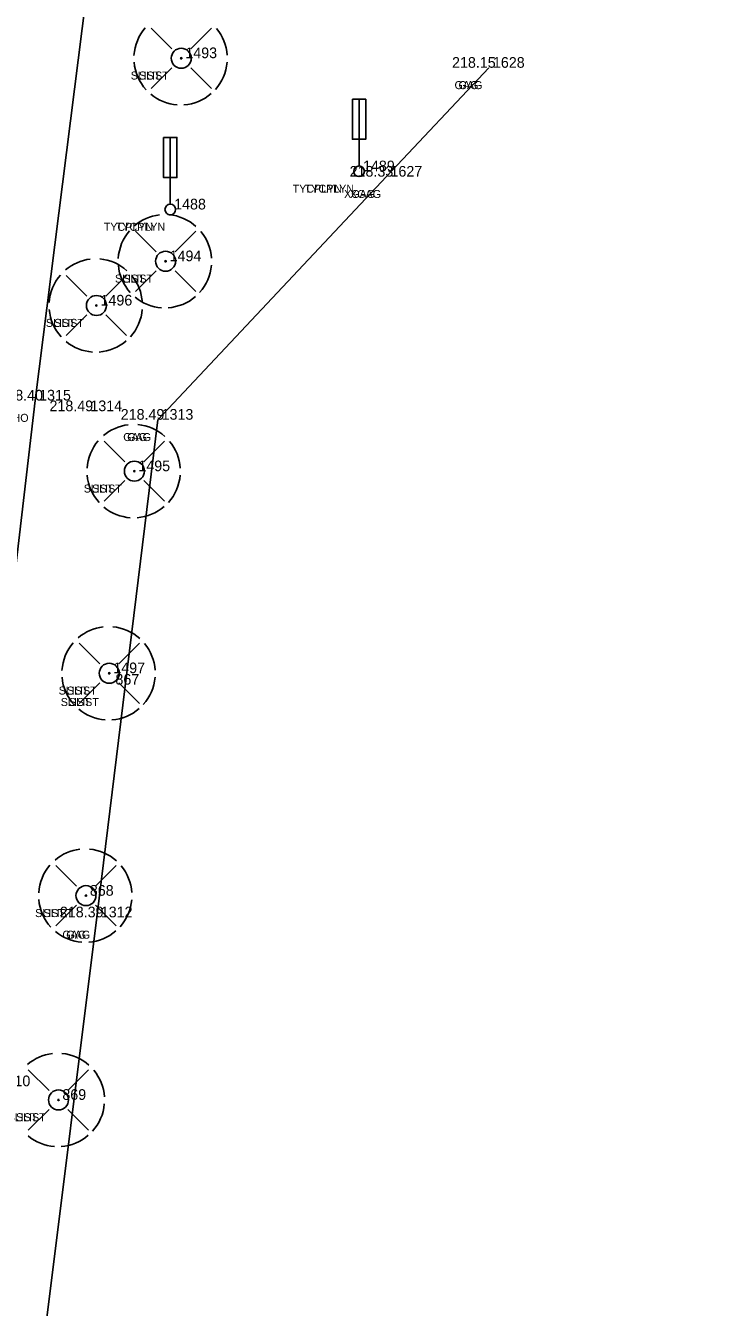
# Model space of a CAD drawing. Extents: x -471047 to -470889, y -1102859 to -1102000.
# Drawn here: x -470945.39 to -470919.5, y -1102458.3 to -1102410.26 of the extents above; entities that cross this region are included whole.
import ezdxf

# ---------------------------------------------------------------- set-up
doc = ezdxf.new("R2010")
doc.units = 0
for name, color, linetype in [('Vrstva 1', 7, 'Continuous'), ('Vrstva 11', 7, 'Continuous'), ('Vrstva 16', 7, 'Continuous'), ('Vrstva 34', 7, 'Continuous'), ('Vrstva 35', 7, 'Continuous'), ('Vrstva 36', 7, 'Continuous'), ('Vrstva 38', 7, 'Continuous'), ('Vrstva 6', 7, 'Continuous'), ('Vrstva 8', 7, 'Continuous')]:
    doc.layers.add(name, color=color, linetype=linetype)

msp = doc.modelspace()

# ---------------------------------------------------------------- linework, layer by layer
at = {"layer": 'Vrstva 1'}
for points in [[(-471040.344, -1102858.385), (-471031.676, -1102846.187), (-471026.357, -1102838.629), (-471023.212, -1102833.975), (-471019.21, -1102827.465), (-471016.861, -1102823.272), (-471013.099, -1102815.912), (-471010.824, -1102810.955), (-471007.329, -1102802.292), (-471005.34, -1102796.515), (-471002.842, -1102787.838), (-471001.3, -1102780.997), (-471000.19, -1102774.713), (-470999.247, -1102768.204), (-470998.794, -1102764.784), (-470997.199, -1102751.812), (-470994.899, -1102732.807), (-470992.551, -1102713.262), (-470990.326, -1102694.887), (-470988.122, -1102676.57), (-470985.812, -1102657.305), (-470983.537, -1102638.407), (-470981.386, -1102620.622), (-470979.843, -1102608.014), (-470976.377, -1102579.253), (-470972.945, -1102550.69), (-470970.475, -1102530.206), (-470967.905, -1102508.801), (-470965.053, -1102485.131), (-470962.734, -1102465.9), (-470960.173, -1102444.812), (-470957.795, -1102425.103), (-470954.965, -1102401.839), (-470953.834, -1102392.574), (-470952.33, -1102379.985), (-470950.744, -1102366.853), (-470948.978, -1102352.106), (-470947.037, -1102335.844), (-470944.949, -1102318.462), (-470944.013, -1102310.745), (-470942.39, -1102297.267), (-470939.519, -1102273.45), (-470937.593, -1102257.43), (-470936.064, -1102244.81), (-470934.114, -1102228.634), (-470931.621, -1102207.856), (-470929.536, -1102190.857), (-470926.572, -1102166.31), (-470924.91, -1102152.663), (-470923.413, -1102140.333), (-470921.923, -1102127.669), (-470921.155, -1102120.084), (-470920.446, -1102109.574), (-470919.912, -1102099.137), (-470919.63, -1102088.981), (-470919.523, -1102081.193), (-470919.563, -1102070.395), (-470919.714, -1102064.236), (-470920.134, -1102054.704), (-470920.462, -1102047.615), (-470920.599, -1102044.52), (-470920.743, -1102041.873), (-470921.125, -1102034.455), (-470921.774, -1102030.337), (-470922.418, -1102027.787), (-470923.734, -1102023.93), (-470924.872, -1102021.434), (-470926.752, -1102018.182), (-470927.953, -1102016.45), (-470929.616, -1102014.424), (-470932.252, -1102011.756), (-470935.111, -1102009.425), (-470938.391, -1102007.371), (-470942.651, -1102005.401)], [(-471041.328, -1102857.18), (-471032.144, -1102844.242), (-471027.583, -1102837.763), (-471024.388, -1102833.028), (-471020.451, -1102826.6), (-471018.089, -1102822.378), (-471014.542, -1102815.445), (-471012.233, -1102810.418), (-471009.247, -1102803.108), (-471006.795, -1102796.098), (-471004.315, -1102787.532), (-471002.782, -1102780.723), (-471001.674, -1102774.458), (-471000.75, -1102768.095), (-471000.28, -1102764.601), (-470998.692, -1102751.741), (-470996.378, -1102732.635), (-470994.028, -1102713.058), (-470991.808, -1102694.749), (-470989.616, -1102676.447), (-470987.284, -1102657.013), (-470985.031, -1102638.272), (-470982.87, -1102620.431), (-470981.334, -1102607.933), (-470977.881, -1102579.263), (-470974.429, -1102550.492), (-470971.964, -1102530.054), (-470969.391, -1102508.607), (-470966.54, -1102484.984), (-470964.231, -1102465.853), (-470961.679, -1102444.752), (-470959.304, -1102425.078), (-470956.455, -1102401.634), (-470955.339, -1102392.489), (-470953.812, -1102379.71), (-470952.249, -1102366.808), (-470950.479, -1102352.023), (-470948.536, -1102335.868), (-470946.426, -1102318.233), (-470945.493, -1102310.531), (-470943.864, -1102297.013), (-470940.984, -1102273.071), (-470939.078, -1102257.195), (-470937.559, -1102244.684), (-470935.592, -1102228.353), (-470933.101, -1102207.653), (-470931.011, -1102190.57), (-470928.046, -1102166.021), (-470926.409, -1102152.578), (-470924.898, -1102140.121), (-470923.427, -1102127.544), (-470922.647, -1102119.826), (-470921.919, -1102109.229), (-470921.42, -1102099.134), (-470921.127, -1102089.016), (-470921.023, -1102081.453), (-470921.061, -1102070.468), (-470921.209, -1102064.314), (-470921.666, -1102053.966), (-470922.156, -1102043.345), (-470922.299, -1102039.934), (-470922.637, -1102034.36), (-470923.091, -1102031.241), (-470923.847, -1102028.247), (-470925.083, -1102024.594), (-470926.222, -1102022.086), (-470928.04, -1102018.943), (-470929.138, -1102017.357), (-470930.929, -1102015.175), (-470933.062, -1102013.049), (-470936.379, -1102010.368), (-470939.169, -1102008.662), (-470942.899, -1102006.906), (-470945.661, -1102005.908)], [(-471043.557, -1102855.955), (-471035.129, -1102844.026), (-471029.872, -1102836.499), (-471026.577, -1102831.578), (-471022.675, -1102825.415), (-471020.123, -1102821.053), (-471016.667, -1102814.59), (-471014.208, -1102809.45), (-471011.177, -1102802.451), (-471008.55, -1102795.333), (-471006.082, -1102787.209), (-471004.464, -1102780.376), (-471003.265, -1102774.167), (-471002.327, -1102767.948), (-471001.636, -1102762.527), (-471000.297, -1102751.605), (-470997.959, -1102732.524), (-470995.602, -1102712.802), (-470993.412, -1102694.623), (-470991.21, -1102676.17), (-470988.891, -1102656.857), (-470986.625, -1102638.083), (-470984.455, -1102620.195), (-470982.936, -1102607.733), (-470979.497, -1102579.223), (-470976.023, -1102550.279), (-470973.554, -1102529.822), (-470970.991, -1102508.497), (-470968.146, -1102484.787), (-470965.835, -1102465.72), (-470963.284, -1102444.529), (-470960.91, -1102424.942), (-470958.043, -1102401.343), (-470956.946, -1102392.356), (-470955.396, -1102379.408), (-470953.851, -1102366.636), (-470952.049, -1102351.733), (-470950.124, -1102335.611), (-470948.034, -1102318.083), (-470947.094, -1102310.328), (-470945.421, -1102296.51), (-470942.58, -1102272.848), (-470940.675, -1102256.948), (-470939.176, -1102244.526), (-470937.187, -1102228.174), (-470934.708, -1102207.467), (-470932.621, -1102190.433), (-470929.634, -1102165.778), (-470928.004, -1102152.415), (-470926.45, -1102139.595), (-470925.003, -1102127.418), (-470924.249, -1102119.695), (-470923.515, -1102109.093), (-470923.018, -1102099.069), (-470922.711, -1102088.911), (-470922.643, -1102081.356), (-470922.797, -1102070.414), (-470923.018, -1102064.454), (-470923.52, -1102053.203), (-470923.823, -1102047.529), (-470924.123, -1102041.506), (-470924.462, -1102037.486), (-470924.934, -1102031.904), (-470925.664, -1102028.672), (-470926.771, -1102025.506), (-470927.959, -1102022.914), (-470929.674, -1102020.028), (-470930.76, -1102018.498), (-470932.447, -1102016.478), (-470935.215, -1102013.816), (-470937.644, -1102011.98), (-470940.381, -1102010.371), (-470943.968, -1102008.669), (-470947.145, -1102007.524), (-470950.874, -1102006.74)], [(-471044.756, -1102855.056), (-471036.376, -1102843.177), (-471031.167, -1102835.741), (-471027.859, -1102830.8), (-471023.934, -1102824.593), (-471021.43, -1102820.312), (-471018.011, -1102813.91), (-471015.536, -1102808.75), (-471012.578, -1102801.897), (-471009.95, -1102794.77), (-471007.561, -1102786.914), (-471005.936, -1102780.074), (-471004.727, -1102773.818), (-471003.828, -1102767.827), (-471003.121, -1102762.345), (-471001.787, -1102751.467), (-470999.446, -1102732.348), (-470997.073, -1102712.539), (-470994.902, -1102694.521), (-470992.696, -1102676.023), (-470990.376, -1102656.68), (-470988.131, -1102638.071), (-470985.947, -1102620.018), (-470984.417, -1102607.512), (-470980.993, -1102579.08), (-470977.514, -1102550.137), (-470975.048, -1102529.649), (-470972.488, -1102508.37), (-470969.618, -1102484.508), (-470967.34, -1102465.669), (-470964.767, -1102444.39), (-470962.402, -1102424.781), (-470959.534, -1102401.193), (-470958.432, -1102392.151), (-470956.883, -1102379.208), (-470955.335, -1102366.424), (-470953.535, -1102351.506), (-470951.606, -1102335.399), (-470949.519, -1102317.94), (-470948.575, -1102310.159), (-470946.889, -1102296.144), (-470944.056, -1102272.618), (-470942.139, -1102256.659), (-470940.657, -1102244.341), (-470938.638, -1102227.749), (-470936.19, -1102207.298), (-470934.102, -1102190.255), (-470931.124, -1102165.639), (-470929.492, -1102152.254), (-470927.915, -1102139.252), (-470926.46, -1102127.103), (-470925.74, -1102119.604), (-470925.012, -1102108.913), (-470924.523, -1102099.054), (-470924.217, -1102088.866), (-470924.148, -1102081.334), (-470924.301, -1102070.391), (-470924.518, -1102064.43), (-470924.97, -1102054.435), (-470925.588, -1102041.569), (-470925.963, -1102035.313), (-470926.405, -1102032.225), (-470927.078, -1102029.198), (-470928.123, -1102026.148), (-470929.318, -1102023.558), (-470930.84, -1102020.97), (-470931.868, -1102019.515), (-470933.443, -1102017.605), (-470936.26, -1102014.885), (-470938.429, -1102013.255), (-470941.213, -1102011.639), (-470944.847, -1102009.927), (-470947.723, -1102008.912), (-470951.444, -1102008.161), (-470954.511, -1102007.931), (-470957.895, -1102008.041)]]:
    msp.add_spline(points, degree=3, dxfattribs=at)
at = {"layer": 'Vrstva 11'}
for p, q in [((-470932.889, -1102413.02), (-470932.889, -1102415.52)), ((-470939.966, -1102414.452), (-470939.966, -1102416.952))]:
    msp.add_line(p, q, dxfattribs=at)
for points in [[(-470933.139, -1102413.02), (-470932.639, -1102413.02), (-470932.639, -1102414.52), (-470933.139, -1102414.52)], [(-470940.216, -1102414.452), (-470939.716, -1102414.452), (-470939.716, -1102415.952), (-470940.216, -1102415.952)]]:
    msp.add_lwpolyline(points, close=True, dxfattribs=at)
for centre in [(-470932.889, -1102415.719), (-470939.966, -1102417.151)]:
    msp.add_circle(centre, 0.2, dxfattribs=at)
at = {"layer": 'Vrstva 16'}
for p, q in [((-470939.91, -1102411.129), (-470940.686, -1102410.354)), ((-470939.2, -1102411.129), (-470938.426, -1102410.354)), ((-470939.91, -1102411.839), (-470940.686, -1102412.614)), ((-470939.2, -1102411.839), (-470938.426, -1102412.614)), ((-470940.498, -1102418.735), (-470941.274, -1102417.96)), ((-470939.788, -1102418.735), (-470939.014, -1102417.96)), ((-470940.498, -1102419.445), (-470941.274, -1102420.22)), ((-470939.788, -1102419.445), (-470939.014, -1102420.22)), ((-470943.09, -1102420.394), (-470943.864, -1102419.619)), ((-470942.38, -1102420.394), (-470941.604, -1102419.619)), ((-470943.09, -1102421.104), (-470943.864, -1102421.879)), ((-470942.38, -1102421.104), (-470941.604, -1102421.879)), ((-470941.668, -1102426.603), (-470942.442, -1102425.828)), ((-470940.958, -1102426.603), (-470940.182, -1102425.828)), ((-470941.668, -1102427.313), (-470942.442, -1102428.088)), ((-470940.958, -1102427.313), (-470940.182, -1102428.088)), ((-470942.61, -1102434.178), (-470943.384, -1102433.403)), ((-470941.9, -1102434.178), (-470941.124, -1102433.403)), ((-470942.61, -1102434.888), (-470943.384, -1102435.663)), ((-470941.9, -1102434.888), (-470941.124, -1102435.663)), ((-470943.482, -1102442.511), (-470944.256, -1102441.736)), ((-470942.772, -1102442.511), (-470941.996, -1102441.736)), ((-470943.482, -1102443.221), (-470944.256, -1102443.996)), ((-470942.772, -1102443.221), (-470941.996, -1102443.996)), ((-470944.512, -1102450.168), (-470945.288, -1102449.393)), ((-470943.802, -1102450.168), (-470943.028, -1102449.393)), ((-470944.512, -1102450.878), (-470945.288, -1102451.653)), ((-470943.802, -1102450.878), (-470943.028, -1102451.653))]:
    msp.add_line(p, q, dxfattribs=at)
for centre, radius in [((-470939.555, -1102411.484), 0.375), ((-470939.555, -1102411.484), 0.025), ((-470939.555, -1102411.484), 0.025), ((-470940.143, -1102419.09), 0.375), ((-470940.143, -1102419.09), 0.025), ((-470940.143, -1102419.09), 0.025), ((-470942.734, -1102420.749), 0.375), ((-470942.734, -1102420.749), 0.025), ((-470942.734, -1102420.749), 0.025), ((-470941.312, -1102426.958), 0.375), ((-470941.312, -1102426.958), 0.025), ((-470941.312, -1102426.958), 0.025), ((-470942.254, -1102434.533), 0.375), ((-470942.254, -1102434.533), 0.025), ((-470942.254, -1102434.533), 0.025), ((-470943.126, -1102442.866), 0.375), ((-470943.126, -1102442.866), 0.025), ((-470943.126, -1102442.866), 0.025), ((-470944.157, -1102450.523), 0.375), ((-470944.157, -1102450.523), 0.025), ((-470944.157, -1102450.523), 0.025)]:
    msp.add_circle(centre, radius, dxfattribs=at)
for centre, start, end in [((-470939.58, -1102411.484), 139.23, 176.4602), ((-470939.58, -1102411.484), 3.8615, 39.6013), ((-470939.58, -1102411.484), 184.9408, 222.2827), ((-470939.58, -1102411.484), 318.1086, 355.0481), ((-470939.58, -1102411.484), 274.1732, 310.7861), ((-470939.58, -1102411.484), 230.4703, 265.8356), ((-470940.169, -1102419.09), 96.7144, 130.447), ((-470940.169, -1102419.09), 48.1897, 84.9117), ((-470940.169, -1102419.09), 139.23, 176.4602), ((-470940.169, -1102419.09), 3.8615, 39.6013), ((-470942.759, -1102420.749), 96.7144, 130.447), ((-470942.759, -1102420.749), 48.1897, 84.9117), ((-470940.169, -1102419.09), 184.9408, 222.2827), ((-470940.169, -1102419.09), 318.1086, 355.0481), ((-470942.759, -1102420.749), 139.23, 176.4602), ((-470942.759, -1102420.749), 3.8615, 39.6013), ((-470940.169, -1102419.09), 230.4703, 265.8356), ((-470940.169, -1102419.09), 274.1732, 310.7861), ((-470942.759, -1102420.749), 184.9408, 222.2827), ((-470942.759, -1102420.749), 318.1086, 355.0481), ((-470942.759, -1102420.749), 230.4703, 265.8356), ((-470942.759, -1102420.749), 274.1732, 310.7861), ((-470941.338, -1102426.958), 96.7144, 130.447), ((-470941.338, -1102426.958), 48.1897, 84.9117), ((-470941.338, -1102426.958), 139.23, 176.4602), ((-470941.338, -1102426.958), 3.8615, 39.6013), ((-470941.338, -1102426.958), 184.9408, 222.2827), ((-470941.338, -1102426.958), 318.1086, 355.0481), ((-470941.338, -1102426.958), 230.4703, 265.8356), ((-470941.338, -1102426.958), 274.1732, 310.7861), ((-470942.28, -1102434.533), 96.7144, 130.447), ((-470942.28, -1102434.533), 48.1897, 84.9117), ((-470942.28, -1102434.533), 139.23, 176.4602), ((-470942.28, -1102434.533), 3.8615, 39.6013), ((-470942.28, -1102434.533), 184.9408, 222.2827), ((-470942.28, -1102434.533), 318.1086, 355.0481), ((-470942.28, -1102434.533), 274.1732, 310.7861), ((-470942.28, -1102434.533), 230.4703, 265.8356), ((-470943.152, -1102442.866), 96.7144, 130.447), ((-470943.152, -1102442.866), 48.1897, 84.9117), ((-470943.152, -1102442.866), 139.23, 176.4602), ((-470943.152, -1102442.866), 3.8615, 39.6013), ((-470943.152, -1102442.866), 184.9408, 222.2827), ((-470943.152, -1102442.866), 318.1086, 355.0481), ((-470943.152, -1102442.866), 230.4703, 265.8356), ((-470943.152, -1102442.866), 274.1732, 310.7861), ((-470944.182, -1102450.523), 96.7144, 130.447), ((-470944.182, -1102450.523), 48.1897, 84.9117), ((-470944.182, -1102450.523), 3.8615, 39.6013), ((-470944.182, -1102450.523), 318.1086, 355.0481), ((-470944.182, -1102450.523), 230.4703, 265.8356), ((-470944.182, -1102450.523), 274.1732, 310.7861)]:
    msp.add_arc(centre, 1.75, start, end, dxfattribs=at)
at = {"layer": 'Vrstva 34'}
for p, q in [((-470939.55, -1102411.48), (-470939.55, -1102411.48)), ((-470928.02, -1102411.84), (-470928.02, -1102411.84)), ((-470932.89, -1102415.72), (-470932.89, -1102415.72)), ((-470931.86, -1102415.92), (-470931.86, -1102415.92)), ((-470939.97, -1102417.15), (-470939.97, -1102417.15)), ((-470940.14, -1102419.09), (-470940.14, -1102419.09)), ((-470942.73, -1102420.75), (-470942.73, -1102420.75)), ((-470945.03, -1102424.31), (-470945.03, -1102424.31)), ((-470943.11, -1102424.71), (-470943.11, -1102424.71)), ((-470940.44, -1102425.03), (-470940.44, -1102425.03)), ((-470941.31, -1102426.96), (-470941.31, -1102426.96)), ((-470942.25, -1102434.53), (-470942.25, -1102434.53)), ((-470942.17, -1102434.96), (-470942.17, -1102434.96)), ((-470943.13, -1102442.87), (-470943.13, -1102442.87)), ((-470942.72, -1102443.68), (-470942.72, -1102443.68)), ((-470944.16, -1102450.52), (-470944.16, -1102450.52))]:
    msp.add_line(p, q, dxfattribs=at)
at = {"layer": 'Vrstva 6'}
for p, q in [((-470928.019, -1102411.838), (-470931.865, -1102415.917)), ((-470931.865, -1102415.917), (-470940.437, -1102425.028)), ((-470940.437, -1102425.028), (-470942.718, -1102443.675)), ((-470942.718, -1102443.675), (-470946.028, -1102470.224))]:
    msp.add_line(p, q, dxfattribs=at)
at = {"layer": 'Vrstva 8'}
for p, q in [((-470945.026, -1102424.313), (-470942.48, -1102404.12)), ((-470948.019, -1102449.764), (-470945.026, -1102424.313))]:
    msp.add_line(p, q, dxfattribs=at)

# ---------------------------------------------------------------- texts
at = {"layer": 'Vrstva 35'}
for s, p in [('SLIST', (-470941.45, -1102412.28)), ('SLIST', (-470941.139, -1102412.28)), ('GAG', (-470929.31, -1102412.64)), ('GAG', (-470929.159, -1102412.64)), ('TYCPLYN', (-470935.379, -1102416.52)), ('TYCPLYN', (-470934.929, -1102416.52)), ('XGAG', (-470933.45, -1102416.72)), ('XGAG', (-470933.224, -1102416.72)), ('TYCPLYN', (-470942.459, -1102417.95)), ('TYCPLYN', (-470942.009, -1102417.95)), ('SLIST', (-470942.04, -1102419.89)), ('SLIST', (-470941.729, -1102419.89)), ('SLIST', (-470944.63, -1102421.55)), ('SLIST', (-470944.319, -1102421.55)), ('CHO', (-470946.169, -1102425.11)), ('GAG', (-470941.73, -1102425.83)), ('GAG', (-470941.579, -1102425.83)), ('SLIST', (-470943.21, -1102427.76)), ('SLIST', (-470942.899, -1102427.76)), ('SLIST', (-470944.15, -1102435.33)), ('SLIST', (-470943.839, -1102435.33)), ('SLIST', (-470944.07, -1102435.76)), ('SLIST', (-470943.759, -1102435.76)), ('SLIST', (-470945.03, -1102443.67)), ('SLIST', (-470944.719, -1102443.67)), ('GAG', (-470944.01, -1102444.48)), ('GAG', (-470943.859, -1102444.48)), ('SLIST', (-470946.06, -1102451.32)), ('SLIST', (-470945.749, -1102451.32))]:
    msp.add_text(s, height=0.3, dxfattribs=at).set_placement(p)
at = {"layer": 'Vrstva 36'}
for s, p in [(' 1493', (-470939.55, -1102411.48)), (' 1628', (-470928.02, -1102411.84)), (' 1489', (-470932.89, -1102415.72)), (' 1627', (-470931.86, -1102415.92)), (' 1488', (-470939.97, -1102417.15)), (' 1494', (-470940.14, -1102419.09)), (' 1496', (-470942.73, -1102420.75)), (' 1315', (-470945.03, -1102424.31)), (' 1314', (-470943.11, -1102424.71)), (' 1313', (-470940.44, -1102425.03)), (' 1495', (-470941.31, -1102426.96)), (' 1497', (-470942.25, -1102434.53)), (' 867', (-470942.17, -1102434.96)), (' 868', (-470943.13, -1102442.87)), (' 1312', (-470942.72, -1102443.68)), (' 1310', (-470946.55, -1102450.01)), (' 869', (-470944.16, -1102450.52))]:
    msp.add_text(s, height=0.4, dxfattribs=at).set_placement(p)
at = {"layer": 'Vrstva 38'}
for s, p in [('218.15 ', (-470929.404, -1102411.84)), ('218.33 ', (-470933.243, -1102415.92)), ('218.40 ', (-470946.373, -1102424.31)), ('218.49 ', (-470944.494, -1102424.71)), ('218.49 ', (-470941.824, -1102425.03)), ('218.39 ', (-470944.104, -1102443.68))]:
    msp.add_text(s, height=0.4, dxfattribs=at).set_placement(p)

doc.saveas('drawing.dxf')
